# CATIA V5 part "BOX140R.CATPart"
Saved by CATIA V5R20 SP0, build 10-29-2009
Part number: BOX140R
Bounding box of the stored display mesh (mm): x 0 to 206, y -17.175 to 44.5, z -41.5 to 15
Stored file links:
  C:\Users\Utente\Desktop\IO LAVORO\3D X SITO CF\X SITO\PLASTICA\BOX\BOX140R.CATPart
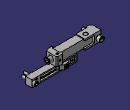
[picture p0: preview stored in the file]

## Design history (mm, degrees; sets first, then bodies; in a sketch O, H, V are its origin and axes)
Set1
  DatumSurface1 to DatumSurface20 "_ZH90/1_head"
  DatumSurface21 to DatumSurface38 "_ZH90/1_screw1"
  DatumSurface39 to DatumSurface56 "_ZH90/1_hand"
  DatumSurface57 to DatumSurface74 "_ZH90/1_screw2"
  DatumSurface75 to DatumSurface95 "_ZH90/1_he"
  DatumSurface96 to DatumSurface110 "_ZH90/1_screw3"
  DatumSurface111 to DatumSurface118 "_ZH90/1_stift1"
  DatumSurface119 to DatumSurface128 "_ZH90/1_stift2"
  DatumSurface129 to DatumSurface590 "_ZH90/01_body"
  DatumSurface591 to DatumSurface608 "_M8-5"
  DatumSurface609 to DatumSurface628 "_ST2"
  DatumSurface629 to DatumSurface674 "_ZH90/01_foot1u"
  DatumSurface675 to DatumSurface697 "_ZH90/01_foot1d"
  DatumSurface698 to DatumSurface715 "_M5-1"
  DatumSurface716 to DatumSurface738 "_ZH90/01_foot2u"
  DatumSurface739 to DatumSurface772 "_ZH90/01_foot2d"
  DatumSurface773 to DatumSurface790 "_M5-2"
Body1 (main body)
